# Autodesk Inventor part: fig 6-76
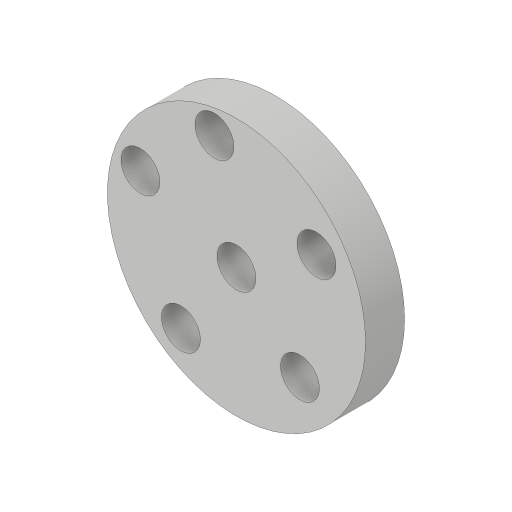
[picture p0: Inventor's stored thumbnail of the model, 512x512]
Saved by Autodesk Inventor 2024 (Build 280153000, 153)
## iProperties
Created: 2018-03
Part Number: fig 6-76
Material: Generic
Document SubType Name: Modeling
Designer: CADCIM 00
Density: 1 g/cm^3
Appearance: Default
Author: CADCIM 00
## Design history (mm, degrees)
sketch "Sketch1"
  geometry: C1 r 16.506 at (0, 0); 1 further point
  constraints: 1 centre point, 1 coincident
extrude "Extrusion1" new body sketch "Sketch1" distance "d0" = 5; taper "d1" = 0 deg
sketch "Sketch3"
  geometry: 2 further points
  constraints: 1 coincident
hole "Hole1" sketch "Sketch3" diameter "d2" = 5; stored, may be unused: countersink angle "d6" = 90 deg, drill point angle "d8" = 118 deg; dims "d3" = 6, "d4" = 4, "d5" = 2, "d7" = 8
sketch "Sketch2"
  geometry: 6 further points
feature "Sketch Driven Pattern1" sketch "Sketch2"
body "Solid1"
